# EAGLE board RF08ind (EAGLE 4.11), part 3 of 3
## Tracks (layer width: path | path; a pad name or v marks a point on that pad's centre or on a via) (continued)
VCC  (via drill 0.61) (continued)
  Bottom 0.508: IC33.14 164.46,90.64 145.41,90.64 140.97,86.19 IC4.16 138.43,86.19 137.79,85.56 v136.52,85.56 | IC1.16 140.33,10.63 146.05,16.35 146.05,34.76 140.33,34.76 IC2.16 | 137.16,133.19 129.53,133.19 128.27,134.46 IC10.14 | 137.16,133.19 138.43,131.92 IC6.16 | IC9.14 128.27,109.05 129.53,107.78 137.16,107.78 138.43,109.05 IC5.14 | v136.52,60.16 137.79,60.16 138.43,60.8 IC3.16
WE\  (via drill 0.61)
  Top 0.254: v113.66,110.32 114.3,110.96 v114.3,139.53 | v75.56,52.54 71.12,48.09 71.12,33.49 RS08.8 | v78.1,52.54 81.91,56.35 81.91,82.38 80.64,83.65 v80.64,109.05
  Bottom 0.254: v113.66,110.32 91.44,110.32 90.17,109.05 IC22.5 87.62,109.05 v80.64,109.05 | v114.3,139.53 118.11,143.34 129.53,143.34 130.81,142.08 IC6.5 | v78.1,52.54 v75.56,52.54
WLS  (via drill 0.61)
  Top 0.254: v225.42,103.97 225.42,89.37 241.93,89.37 242.56,90 242.56,93.18 247.01,93.18 248.28,91.91 IC44.11 | v26.67,178.91 26.67,185.25 27.94,186.53 IC37.4 | v134.62,177.64 136.52,175.73 v136.52,117.94
  Bottom 0.254: v225.42,103.97 211.45,117.94 v136.52,117.94 121.92,117.94 120.65,119.21 IC9.5 | v26.67,178.91 64.13,178.91 64.77,178.27 97.15,178.27 97.79,178.91 102.87,178.91 105.41,176.37 120.65,176.37 121.92,177.64 v134.62,177.64
WLS\
  Top 0.254: IC9.6 120.01,122.39 122.55,124.93 122.55,136.36 124.45,138.27 124.45,167.47 122.55,169.38 122.55,188.43 116.84,194.15 IC12.13
WRITING  (via drill 0.61)
  Top 0.254: IC41.14 17.14,81.75 17.14,83.02 IC41.13 | v53.34,64.6 58.41,59.52 58.41,33.49 RS08.18 | v122.55,144.62 121.92,143.98 v121.92,137.63 | v205.74,128.74 205.74,103.97 209.55,100.16 209.55,93.81 210.81,92.54 IC42.11 | v122.55,72.22 123.19,72.86 123.19,118.58 123.82,119.21 v123.82,135.72
  Bottom 0.254: IC41.14 16.51,81.11 15.23,79.84 8.25,79.84 8.25,75.4 15.87,67.78 50.16,67.78 v53.34,64.6 56.51,67.78 113.66,67.78 118.11,72.22 v122.55,72.22 | v122.55,144.62 120.65,144.62 IC10.5 | v121.92,137.63 v123.82,135.72 129.53,135.72 | 129.53,135.72 130.81,134.46 IC6.2 | v205.74,128.74 198.75,135.72 129.53,135.72

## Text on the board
Top: RF08 | VRS
Bottom: RF08 | VRS
tDocu: FIELD | DISC EXT MEM ADDR | 3 | 2 | 1 | 8 | 7 | 6 | 5 | 4 | 3 | 2 | 1 | 0 | DISC MEM ADDR | 0 | 1 | 2 | 3 | 4 | 5 | 6 | 7 | 8 | 9 | 10 | 11 | DISC MEM BUFF | 0 | 1 | 2 | 3 | 4 | 5 | 6 | 7 | 8 | 9 | 10 | 11 | CIE | EIE | PIE | DRE | R/W | DBR | DRL | WLS | NXD | WCO | PER | DCF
